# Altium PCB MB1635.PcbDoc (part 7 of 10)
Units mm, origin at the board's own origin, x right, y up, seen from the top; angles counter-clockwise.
Board outline 127 x 97 mm, 6 copper layers (Top Layer, Signal Layer 1, Signal Layer 2, Signal Layer 3, Signal Layer 4, Bottom Layer), stack 1.557 mm thick; 593 components, 478 nets, 2435 pads, 1743 vias.
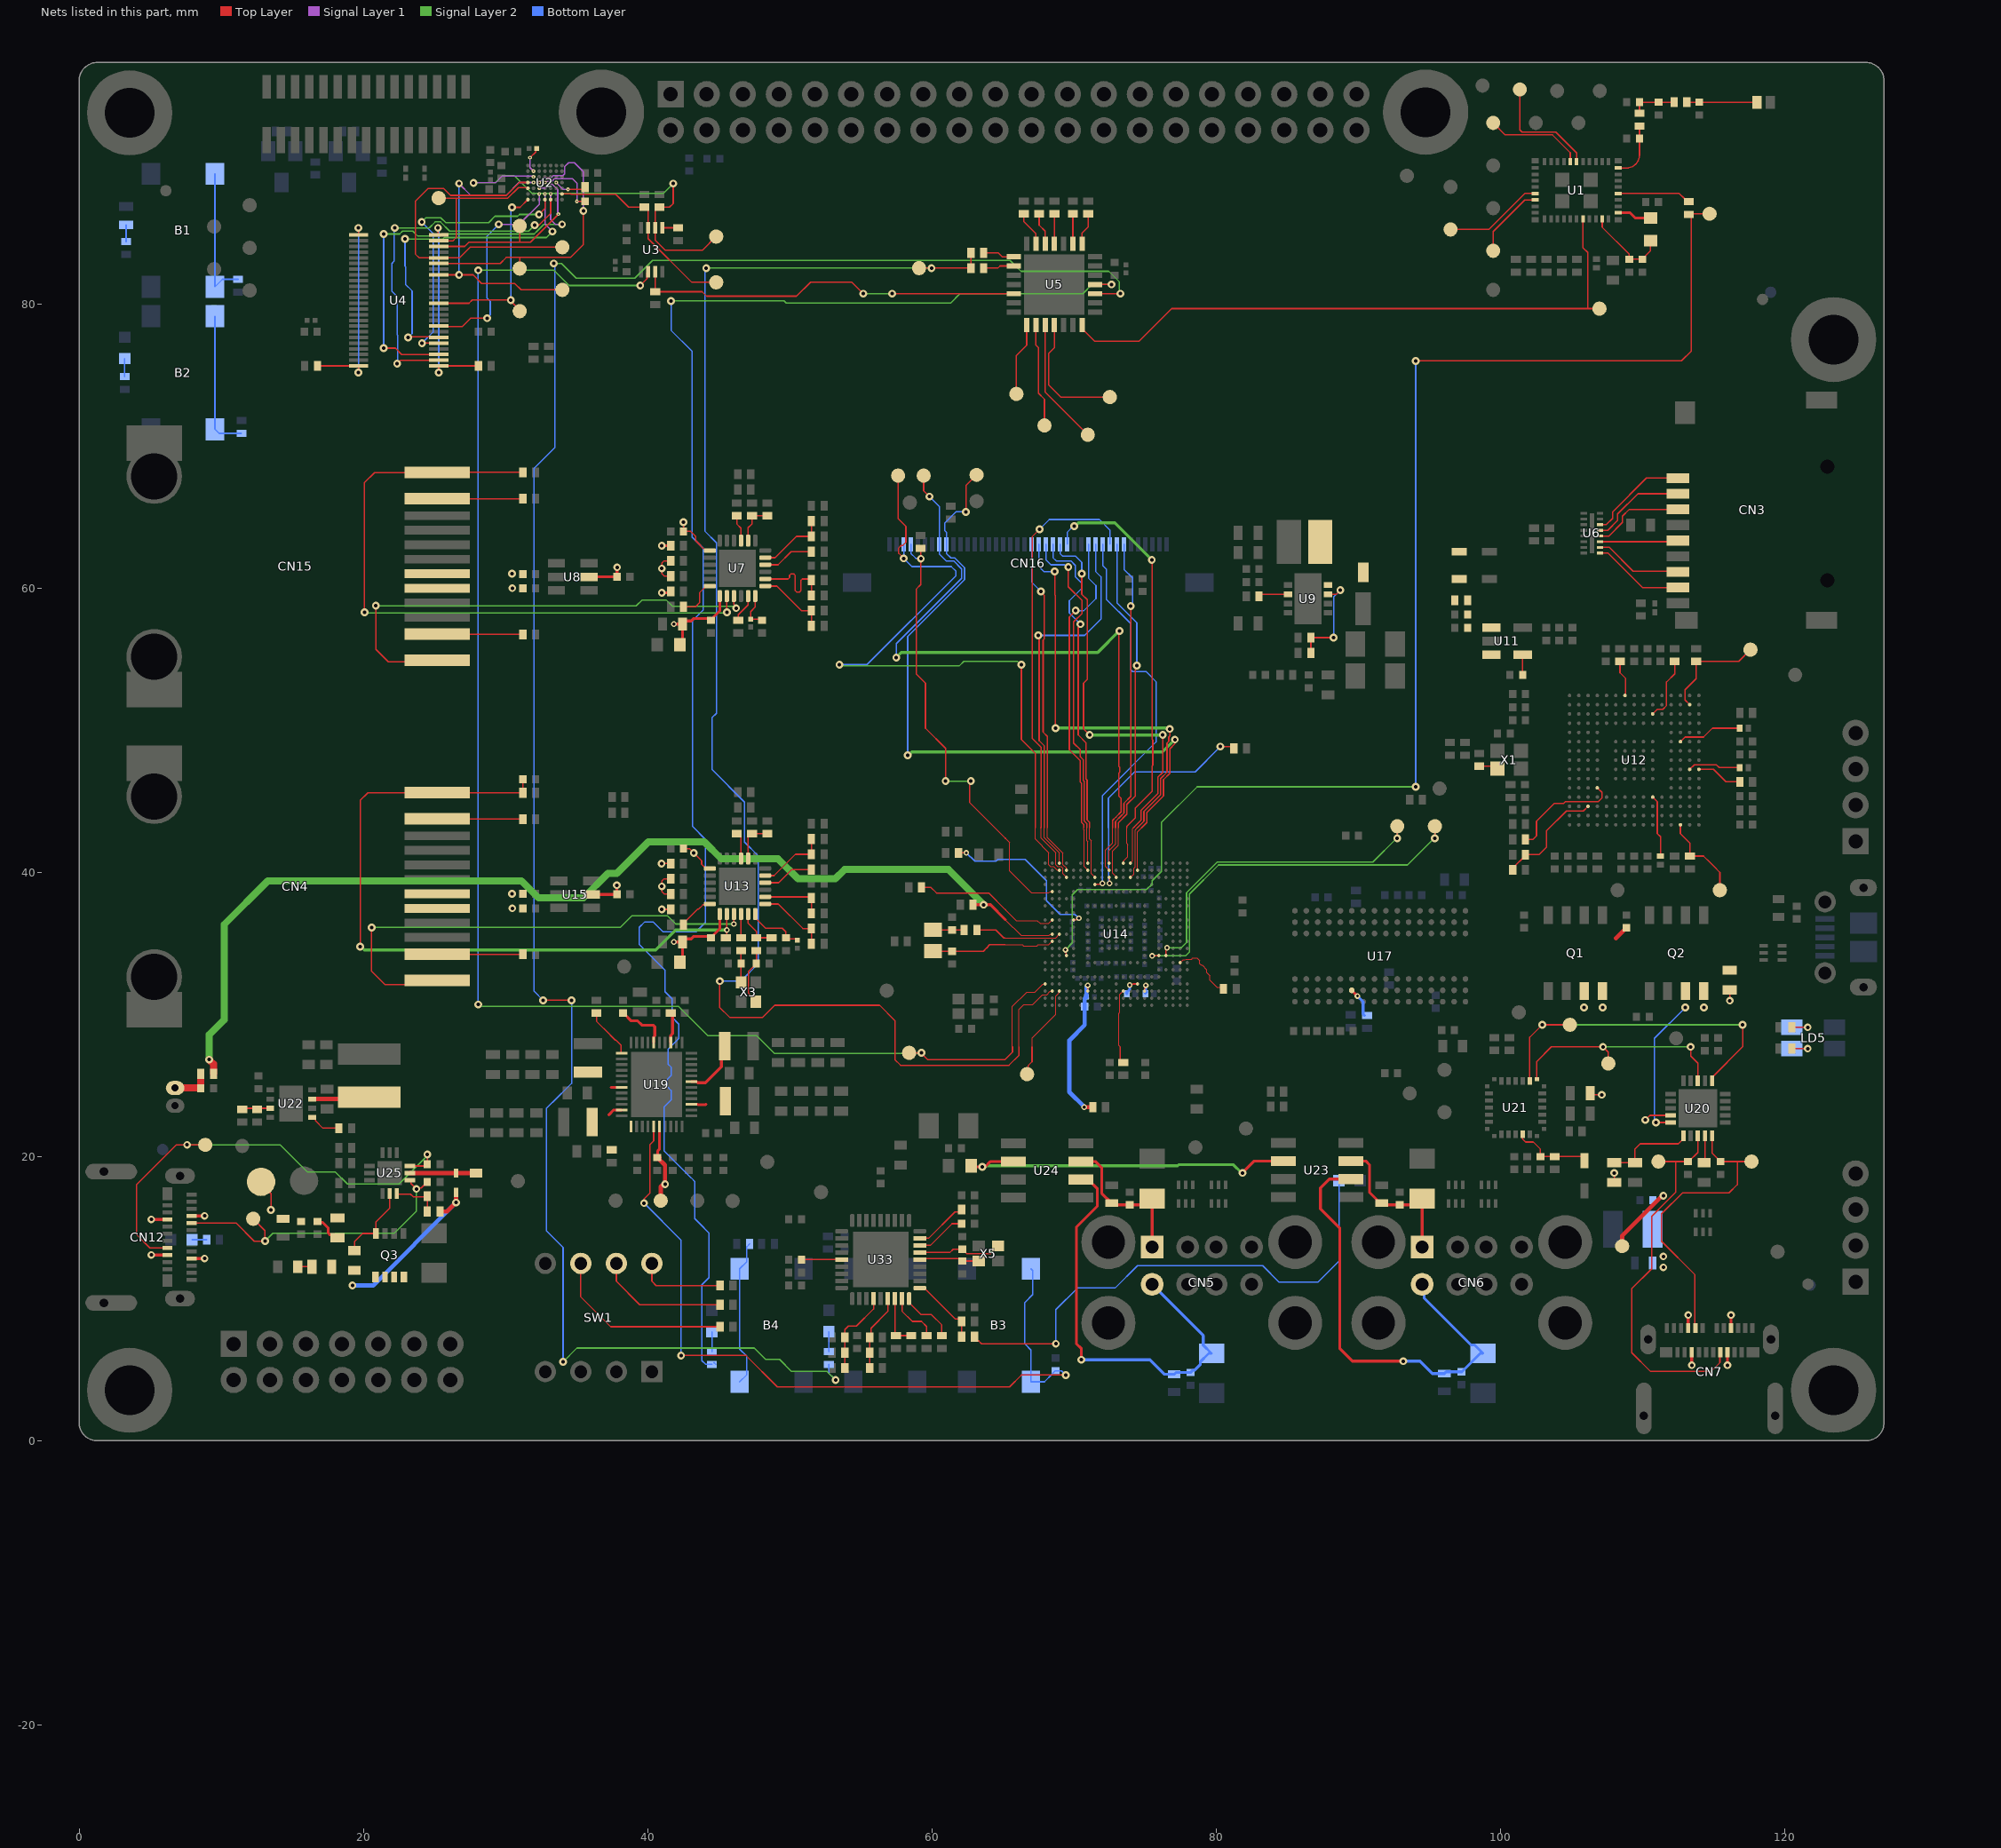
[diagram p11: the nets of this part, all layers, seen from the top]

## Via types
v1: diameter 0.55, hole 0.25, Top Layer to Bottom Layer, 1438 vias
v2: diameter 0.4, hole 0.2, Top Layer to Bottom Layer, 276 vias
v3: diameter 0.26, hole 0.1, Top Layer to Signal Layer 1, tented both sides, 29 vias

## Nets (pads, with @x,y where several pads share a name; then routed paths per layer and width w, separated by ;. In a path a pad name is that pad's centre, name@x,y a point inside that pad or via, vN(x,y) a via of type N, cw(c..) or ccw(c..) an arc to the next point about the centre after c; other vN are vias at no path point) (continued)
LCD_G2: CN16.15 U14.A12 | length 30.4
  Top Layer w0.075: U14.A12@73.475,40.65 73.475,40.775 73.795,41.095 73.795,41.955 73.725,42.025 73.725,43.125
  Top Layer w0.1: 73.725,43.125 73.725,43.249 74.325,43.849 74.325,44.538 75.5,45.713 75.5,47.497 75.55,47.547 75.55,49.33 75.5,49.38 75.5,61.975 v1(75.475,62)
  Signal Layer 2 w0.219: v1(70.025,64.375) 70.094,64.375 70.319,64.6 72.875,64.6 v1(75.475,62)
  Bottom Layer w0.1: CN16.15@69.525,63.1 69.525,63.928 69.972,64.375 v1(70.025,64.375)
LCD_G3: CN16.16 U14.A13 | length 30.2
  Top Layer w0.075: U14.A13@73.975,40.65 74.135,40.81 74.135,43.086 74.174,43.125
  Top Layer w0.1: v1(70.55,61.025) 70.55,59.576 70.937,59.189 70.937,53.587 70.675,53.325 70.675,50.1 v1(71.1,49.675) ; 74.174,43.125 74.25,43.201 74.25,43.208 74.725,43.683 74.725,44.372 75.9,45.547 75.9,46.691 76.25,47.041 v1(76.25,49.675)
  Signal Layer 2 w0.219: v1(71.1,49.675) v1(76.25,49.675)
  Bottom Layer w0.1: CN16.16@69.025,63.1 69.025,62.434 69.2,62.259 70.115,62.259 70.55,61.825 v1(70.55,61.025)
LCD_G4: CN16.17 U14.C8 | length 26.1
  Top Layer w0.075: 71.1,43.125 71.1,42.35 71.221,42.229 71.221,40.752 71.221,40.048 71.221,39.904 U14.C8@71.475,39.65
  Top Layer w0.1: v1(70.45,57.475) 70.45,57.416 70.3,57.266 70.3,49.675 70.853,49.122 70.853,49.06 70.85,49.058 70.85,46.566 70.925,46.491 70.925,43.699 71.1,43.524 71.1,43.125
  Bottom Layer w0.1: CN16.17@68.525,63.1 68.525,62.15 68.75,61.925 69.776,61.925 70.1,61.601 70.1,60.807 70.55,60.357 70.55,59.992 69.675,59.117 69.675,58.25 v1(70.45,57.475)
LCD_G5: CN16.18 U14.A7 | length 24.8
  Top Layer w0.075: 70.9,43.125 70.9,42.225 70.975,42.15 U14.A7@70.975,40.65
  Top Layer w0.1: v1(69.6,61.5) 69.6,60.105 70.575,59.13 70.575,58.225 69.975,57.625 69.975,49.1 70.45,48.625 70.45,48.133 70.65,47.933 70.65,46.483 70.725,46.408 70.725,43.616 70.9,43.441 70.9,43.125
  Bottom Layer w0.1: CN16.18@68.025,63.1 68.025,62 68.375,61.65 69.328,61.65 69.478,61.5 v1(69.6,61.5)
LCD_G6: CN16.19 U14.C13 | length 33.6
  Top Layer w0.075: U14.C13@73.975,39.65 74.221,39.897 74.221,40.296 74.305,40.38 74.305,42.98 74.45,43.125
  Top Layer w0.1: v1(68.65,61.175) 68.65,59.53 68.7,59.48 v1(68.7,50.15) ; 74.45,43.125 74.925,43.6 74.925,44.289 76.1,45.464 76.1,46.608 76.55,47.058 76.55,49.1 76.675,49.225 76.675,49.526 76.744,49.595 v1(76.744,50.1)
  Signal Layer 2 w0.219: v1(68.7,50.15) 68.725,50.175 76.58,50.175 76.655,50.1 v1(76.744,50.1)
  Bottom Layer w0.1: CN16.19@67.525,63.1 67.525,61.53 67.88,61.175 v1(68.65,61.175)
LCD_G7: CN16.20 U14.B4 | length 24.1
  Top Layer w0.075: 68.125,43.125 68.125,42.46 69.225,41.36 69.225,40.55 69.464,40.311 69.464,40.161 U14.B4@69.475,40.15
  Top Layer w0.1: v1@67.655,59.795 67.655,59.74 67.903,59.491 67.903,56.43 67.828,56.355 67.828,49.872 68.125,49.575 68.125,43.125
  Bottom Layer w0.1: CN16.20@67.025,63.1 67.025,60.425 v1(67.675,59.775)
LCD_HSYNC: CN16.32 TP43.1 U14.B14 | length 53
  Top Layer w0.075: U14.B14@74.475,40.15 74.475,42.85 74.75,43.125
  Top Layer w0.1: v1(62.4,65.375) 62.4,67.23 TP43.1@63.145,67.975 ; 74.75,43.125 75.125,43.5 75.125,44.206 76.3,45.381 76.3,46.525 76.75,46.975 76.75,48.7 77.1,49.05 v1(77.1,49.35)
  Signal Layer 2 w0.219: v1(58.3,48.25) 58.369,48.25 58.594,48.475 76.225,48.475 v1(77.1,49.35)
  Bottom Layer w0.1: v1(58.3,48.25) 58.3,56.6 62.3,60.6 62.3,61.441 61.616,62.125 61.34,62.125 61.025,62.44 CN16.32@61.025,63.1 61.025,63.949 60.9,64.074 60.9,64.565 61.71,65.375 v1(62.4,65.375)
LCD_INT: CN16.38 TP42.1 U14.B3 | length 51.5
  Top Layer w0.075: 67.275,43.125 67.275,42.348 68.225,41.398 68.225,40.55 68.35,40.425 68.351,40.425 68.373,40.404 68.571,40.404 68.825,40.15 U14.B3@68.975,40.15
  Top Layer w0.1: TP42.1@57.625,67.925 57.625,64.904 58.175,64.353 58.175,63.225 57.955,63.005 57.855,63.005 57.65,62.8 57.671,62.779 57.671,62.454 v1(58.025,62.1) ; v1(66.3,54.625) 66.3,49.35 67.278,48.372 67.278,43.343 67.275,43.34 67.275,43.125
  Signal Layer 2 w0.1: v1(53.5,54.625) 53.575,54.55 61.95,54.55 62.25,54.85 66.016,54.85 66.241,54.625 v1(66.3,54.625)
  Bottom Layer w0.1: v1(53.5,54.625) 55.442,54.625 61.7,60.883 61.7,61.192 61.367,61.525 58.6,61.525 v1(58.025,62.1) CN16.38@58.025,63.1
LCD_R2: CN16.7 U14.A10 | length 23.4
  Top Layer w0.075: U14.A10@72.475,40.65 72.475,41.55 72.925,42 72.925,43.125
  Top Layer w0.1: 72.925,43.125 72.925,43.58 73.32,43.975 73.32,43.98 73.52,44.18 73.52,44.864 74,45.344 v1(74,58.75)
  Bottom Layer w0.1: CN16.7@73.525,63.1 73.525,61.325 74.125,60.725 74.125,58.997 74,58.872 v1(74,58.75)
LCD_R3: CN16.8 U14.C11 | length 24.8
  Top Layer w0.075: U14.C11@72.975,39.65 72.975,39.681 72.721,39.935 72.721,41.521 73.125,41.925 73.125,43.125
  Top Layer w0.1: 73.125,43.125 73.125,43.497 73.725,44.097 73.725,44.786 74.325,45.386 74.325,54.266 74.339,54.28 74.339,54.464 v1(74.425,54.55)
  Bottom Layer w0.1: CN16.8@73.025,63.1 73.025,58.973 74.425,57.573 v1(74.425,54.55)
LCD_R4: CN16.9 U14.C4 | length 32.4
  Top Layer w0.075: 67.675,43.125 67.675,42.429 68.725,41.379 68.725,40.525 68.85,40.4 69.1,40.4 69.225,40.275 69.225,39.9 U14.C4@69.475,39.65
  Top Layer w0.1: v1(67.579,64.147) 67.053,63.621 67.053,49.447 67.678,48.822 67.678,43.177 67.675,43.174 67.675,43.125
  Bottom Layer w0.1: v1(67.579,64.147) 68.268,64.836 71.794,64.836 72.525,64.105 CN16.9@72.525,63.1
LCD_R5: CN16.10 U14.D8 | length 28
  Top Layer w0.09: U14.D8@71.475,39.15 v2@71.95,39.15
  Bottom Layer w0.09: v2(72,39.225) 72,43.125
  Bottom Layer w0.1: 72,43.125 72,45.4 75.775,49.175 75.775,53.425 75.075,54.125 74.13,54.125 74,54.255 74,57.5 72.275,59.225 72.275,61.355 72.025,61.605 CN16.10@72.025,63.1
LCD_R6: CN16.11 U14.A3 | length 26.9
  Top Layer w0.075: 67.9,43.125 67.9,42.444 68.975,41.369 U14.A3@68.975,40.65
  Top Layer w0.1: v1@67.55,56.6 67.55,49.275 67.9,48.925 67.9,43.125
  Bottom Layer w0.1: v1(67.478,56.678) 70.753,56.678 71.9,57.825 71.9,60.802 71.525,61.177 CN16.11@71.525,63.1
LCD_R7: CN16.12 U14.B7 | length 24.8
  Top Layer w0.075: 70.7,43.125 70.7,43 70.725,42.975 70.725,40.4 U14.B7@70.975,40.15
  Top Layer w0.1: v1(70.125,58.425) 69.675,57.975 69.675,48.625 70.45,47.85 70.45,46.348 70.525,46.273 70.525,43.533 70.7,43.358 70.7,43.125
  Bottom Layer w0.1: v1(70.125,58.425) 70.7,58.425 71.55,59.275 71.55,60.18 71.025,60.705 CN16.12@71.025,63.1
LCD_RST: CN16.37 R58.1 U14.E2 | length 31.9
  Top Layer w0.075: 65.175,42.4 65.46,42.115 65.46,40.115 67.009,38.566 68.222,38.566 68.305,38.649 68.474,38.649 U14.E2@68.475,38.65
  Top Layer w0.1: R58.1@59.2,62.8 59.225,62.775 v1(59.225,62.075) 59.225,60.25 58.9,59.925 58.9,53.975 59.55,53.325 59.55,50.15 60.971,48.729 v1(60.971,46.425) ; v1(62.75,46.425) 62.664,46.339 62.664,46.155 62.65,46.141 62.65,44.925 65.175,42.4
  Signal Layer 2 w0.1: v1(60.971,46.425) v1(62.75,46.425)
  Bottom Layer w0.1: CN16.37@58.525,63.1 58.525,62.451 58.862,62.114 59.186,62.114 v1(59.225,62.075)
LCD_VSYNC: CN16.33 TP37.1 U14.B10 | length 50.2
  Top Layer w0.075: U14.B10@72.475,40.15 72.225,40.4 72.225,41.575 72.725,42.075 72.725,43.125
  Top Layer w0.1: TP37.1@59.425,67.925 59.425,66.85 v1(59.825,66.45) ; 72.725,43.125 72.725,43.663 72.963,43.9 72.963,43.905 73.32,44.262 73.32,45.205 73.15,45.375 73.15,46.974 73.225,47.049 73.225,47.401 73.15,47.476 73.15,56.95 v1(73.2,57)
  Signal Layer 2 w0.219: v1(57.5,55.125) 57.846,55.471 71.671,55.471 v1(73.2,57)
  Bottom Layer w0.1: v1(57.5,55.125) 57.5,56.1 62.1,60.7 62.1,61.358 61.533,61.925 61.009,61.925 60.525,62.409 CN16.33@60.525,63.1 60.525,65.75 v1(59.825,66.45)
LED_G: R183.1 U5.3 | length 147.3
  Top Layer w0.1: v1(32.65,31) v1(34.65,31) ; U5.3@71.475,80.725 v1(73.275,80.725)
  Signal Layer 2 w0.1: v1(33.4,82.85) 33.95,82.85 34.975,81.825 39.105,81.825 40.355,83.075 65.5,83.075 66.275,82.3 72.45,82.3 73.2,81.55 73.2,80.8 v1(73.275,80.725) ; v1(34.05,5.55) 35.025,6.525 47.5,6.525 48.3,5.725 49.283,5.725 50.133,4.875 52.634,4.875 53.225,4.284 v1(53.225,4.275)
  Bottom Layer w0.1: v1(32.65,31) 32,31.65 32,68.425 33.475,69.9 33.475,82.775 v1(33.4,82.85) ; v1(34.05,5.55) 34.05,13.6 32.875,14.775 32.875,23.4 33.3,23.825 33.326,23.825 34.65,25.149 v1(34.65,31) ; R183.1@52.75,5.375 52.75,4.75 v1(53.225,4.275)
LED_Y: R184.1 U5.4 | length 118.5
  Top Layer w0.1: U5.4@71.475,81.375 v1(72.65,81.375)
  Signal Layer 2 w0.1: v1(41.65,80.2) 41.675,80.225 49.6,80.225 49.75,80.075 61.325,80.075 61.975,80.725 70.625,80.725 71.275,81.375 v1(72.65,81.375)
  Bottom Layer w0.1: v1(41.65,80.2) 41.65,78.15 43.125,76.675 43.125,63.6 43.905,62.82 43.905,58.455 43.15,57.7 43.15,43.25 44.075,42.325 44.075,36.476 43.419,35.82 41.08,35.82 40.38,36.52 39.8,36.52 39.41,36.13 39.41,35.914 39.4,35.904 39.4,34.949 41.227,33.122 41.227,31.601 41.725,31.103 41.725,29.8 42.2,29.325 42.2,28.3 41.45,27.55 41.45,26.5 41.65,26.3 41.65,25.7 41.375,25.425 41.375,24.925 41.65,24.65 41.65,23.975 41.15,23.475 41.15,20.425 43.075,18.5 ; 43.076,18.5 43.325,18.251 43.325,15.627 43.625,15.327 43.625,15.325 44.325,14.625 44.325,11.475 43.825,10.975 43.825,5.642 44.084,5.383 44.517,5.383 R184.1@44.525,5.375 ; R184.1@44.662,5.513 R184.1@44.8,5.375
LPO_32: R190.1 TP15.1 U14.P4 | length 94.6
  Top Layer w0.09: v2@69.45,34.55 69.45,34.175 U14.P4@69.475,34.15
  Top Layer w0.1: v1(94.05,76) 112.75,76 113.45,76.7 113.45,86.125 113.363,86.212 113.5,86.35 TP15.1@114.725,86.35
  Signal Layer 2 w0.09: v2(69.4,34.55) 69.875,35.025 69.875,38.4 70.25,38.775 75.1,38.775 75.5,39.175 75.5,39.425 76.15,40.075 76.15,43.125
  Signal Layer 2 w0.1: 76.15,43.125 76.15,43.5 78.675,46.025 v1(94.05,46.025)
  Bottom Layer w0.1: v1(94.05,46.025) v1(94.05,76)
MCO1: TP54.1 U3.2 U14.V1 | length 111.2
  Top Layer w0.075: 65.675,27.725 65.675,30.575 66.675,31.575 67.261,31.575 67.813,32.127 67.952,32.127 U14.V1@67.975,32.15
  Top Layer w0.1: v1(39.475,81.3) 39.959,81.784 39.959,82.184 U3.2@40.04,82.265 ; TP54.1@58.4,27.3 v1(59.275,27.3) ; v1@59.225,27.3 59.7,26.825 65.15,26.825 65.675,27.35 65.675,27.725
  Signal Layer 2 w0.1: v1(28.076,30.701) 28.076,30.699 28.2,30.575 42.175,30.575 44.25,28.5 47.7,28.5 48.95,27.25 59.175,27.25 v1@59.225,27.3 ; v1(28.076,82.379) 33.396,82.379 34.475,81.3 v1(39.475,81.3)
  Bottom Layer w0.1: v1(28.076,30.701) 28.076,82.301 v1(28.076,82.379)
MCP_INT: R12.1 R19.1 TP23.1 U14.W2 | length 107.9
  Top Layer w0.075: 66.125,27.725 66.125,30.35 66.475,30.7 67.103,30.7 67.8,31.397 68.097,31.397 68.327,31.627 68.452,31.627 U14.W2@68.475,31.65
  Top Layer w0.1: v1(45.075,32.35) 45.075,30.5 45.775,29.8 48.1,29.8 48.95,30.65 56.325,30.65 57.4,29.575 57.4,26.825 57.8,26.425 65.425,26.425 66.125,27.125 66.125,27.725 ; TP23.1@59.1,82.525 v1(59.975,82.525) R19.1@62.75,82.525 R12.1@62.75,83.6
  Signal Layer 2 w0.1: v1(44.125,82.525) v1(59.975,82.525)
  Bottom Layer w0.1: v1(44.125,82.525) 44.039,82.439 44.039,82.255 44.025,82.241 44.025,64.025 44.85,63.2 44.85,51.2 44.525,50.875 44.525,47.25 46.825,44.95 46.825,42.125 47.775,41.175 47.775,33.55 46.575,32.35 v1(45.075,32.35)
MCP_IO2: R13.2 U3.3 U5.19 | length 27.5
  Top Layer w0.1: U3.3@40.54,82.265 R13.2@40.54,80.865 43.835,80.865 44.15,80.55 50.475,80.55 51.467,81.542 54.358,81.542 v1(55.175,80.725) ; v1(57.2,80.725) U5.19@65.775,80.725
  Signal Layer 2 w0.1: v1(55.175,80.725) v1(57.2,80.725)
MCP_IO11: TP30.1 U1.28 U5.28 | length 44.4
  Top Layer w0.1: U5.28@70.575,78.525 70.575,78.25 71.45,77.375 74.575,77.375 76.875,79.675 106.15,79.675 ; U1.28@105.825,85.975 105.825,83.95 106.15,83.625 106.15,79.675 ; TP30.1@106.975,79.675 106.15,79.675
NetB1_3: B1.3 B1.4 R173.1 | length 9.8
  Bottom Layer w0.1: B1.3@9.555,89.163 B1.4@9.555,81.213 10.08,81.738 R173.1@11.18,81.738
NetB2_3: B2.3 B2.4 R175.1 | length 9.9
  Bottom Layer w0.1: B2.3@9.555,79.138 B2.4@9.555,71.188 9.843,70.9 R175.1@11.425,70.9
NetB3_3: B3.3 B3.4 C228.2 U19.17 | length 57.1
  Top Layer w0.1: v1(39.75,16.725) 39.75,17.025 40.15,17.425 40.15,20.825 40.425,21.1 U19.17@40.425,22.125 ; v1(42.35,6) 46.925,6 49.125,3.8 65.475,3.8 66.3,4.625 v1(69.425,4.625)
  Bottom Layer w0.1: v1(39.75,16.725) 42.35,14.125 v1(42.35,6) ; B3.3@66.975,12.1 67.1,11.975 67.1,10.284 66.543,9.728 66.543,6.825 66.975,6.393 B3.4@66.975,4.15 67.925,4.15 68.47,4.695 68.47,4.72 68.675,4.925 C228.2@68.7,4.925 69.125,4.925 v1(69.425,4.625)
NetB4_3: B4.3 B4.4 R182.1 | length 10.4
  Bottom Layer w0.1: B4.3@46.475,4.15 46.983,4.658 46.983,5.942 46.475,6.45 B4.4@46.475,12.1 46.982,12.607 46.982,13.657 R182.1@47.175,13.85
NetC1_2: C1.2 C2.2 R1.2 R2.1 | length 3.2
  Top Layer w0.1: R2.1@109.8,93.425 C1.2@109.8,94.2 R1.2@112.225,94.2
NetC3_2: C3.2 L1.1 R1.1 | length 4.9
  Top Layer w0.1: R1.1@113.125,94.2 C3.2@114,94.2 L1.1@118.05,94.2
NetC4_2: C4.2 R2.2 U1.41 | length 4.1
  Top Layer w0.1: U1.41@108.3,89.575 108.888,89.575 ccw(c108.888,90.487) 109.8,90.487 C4.2@109.8,91.65 R2.2@109.8,92.525
NetC5_2: C5.2 U2.F2 | length 1.9
  Top Layer w0.1: v3(31.725,90.3) 32.125,90.7 32.125,90.875 C5.2@32.2,90.95
  Signal Layer 1 w0.1: v3(31.725,90.3) 31.725,89.6 v3(31.975,89.35)
NetC14_2: C14.2 U2.D4 | length 4.4
  Top Layer w0.1: v3(35.025,87.225) C14.2@35.6,87.225
  Signal Layer 1 w0.1: v3(32.775,88.55) 32.818,88.55 32.898,88.63 33.25,88.63 33.45,88.83 34.7,88.83 35.025,88.505 v3(35.025,87.225)
NetC20_2: C20.2 C21.2 L2.2 U1.31 | length 6.1
  Top Layer w0.1: U1.31@107.175,85.975 107.175,85.4 109.075,83.5 C20.2@109.075,83.15 C21.2@110,83.15 110,83.175 110.575,83.75 L2.2@110.575,84.45
NetC28_2: C28.2 C32.2 C33.1 C35.2 C37.2 C39.1 CN15.5 CN15.6 L4.1 R37.2 R39.2 R40.2 R42.2 U7.1 U7.19 U8.5 | length 15.5
  Top Layer w0.1: R40.2@41.625,60.85 41.175,60.85 41,61.025 v1(41,61.388) 41,61.775 41.15,61.925 R39.2@41.625,61.925 ; v1(42.525,64.65) C28.2@42.525,64 43.025,64 43.375,63.65 43.375,63.35 44.075,62.65 U7.19@44.375,62.65
  Top Layer w0.2: U8.5@35.875,60.8 C33.1@37.85,60.8 v1(37.85,61.475) ; v1(41,59.675) 41.525,59.675 R42.2@41.625,59.775 ; v1(41,63) R37.2@41.625,63 ; v2(41.85,57.475) C39.1@42.45,57.475 ; L4.1@42.275,56.05 42.45,56.225 C39.1@42.45,57.475 ; U7.1@45.075,59.45 45.075,58.4 44.45,57.775 44.35,57.875 43.25,57.875 43.075,57.7 42.675,57.7 C39.1@42.45,57.475
  other v1: 30.475,60.005 30.45,61.03
NetC36_1: C36.1 C41.2 R45.2 U11.1 U11.3
NetC38_2: C38.2 C40.2 U7.6 | length 2.6
  Top Layer w0.1: U7.6@47.575,59.45 47.575,58.675 47.25,58.35 C40.2@47.25,57.825 47.975,57.825 C38.2@48.05,57.75
NetC55_2: C55.2 U11.4 | length 1.4
  Top Layer w0.1: C55.2@101.575,53.9 U11.4@101.575,55.325
NetC60_2: C60.2 U12.F13 | length 4.6
  Top Layer w0.1: U12.F13@112.675,49.2 113,49.525 114.3,49.525 114.925,50.15 C60.2@116.85,50.15
NetC64_2: C64.2 U12.J14 | length 3.7
  Top Layer w0.1: U12.J14@113.325,47.25 113.65,47.575 115.2,47.575 115.4,47.375 C64.2@116.85,47.375
NetC71_2: C71.2 C80.2 C81.1 C85.2 C89.2 C91.1 CN4.5 CN4.6 L5.1 R92.2 R95.2 R97.2 R99.2 U13.1 U13.19 U15.5 | length 14.7
  Top Layer w0.1: v1(40.975,40.625) R92.2@41.625,40.625 ; v1(41,37.4) R99.2@41.625,37.4 ; R97.2@41.625,38.475 41.175,38.475 41,38.65 v1(41,39.013) 41,39.4 41.15,39.55 R95.2@41.625,39.55 ; C71.2@42.525,41.675 42.95,41.675 v1(43.25,41.375) 43.8,40.825 43.8,40.575 44.1,40.275 U13.19@44.375,40.275
  Top Layer w0.2: U15.5@36.05,38.45 C81.1@37.85,38.45 37.825,38.475 v1(37.825,39.1) ; v2(41.85,35.1) C91.1@42.45,35.1 ; L5.1@42.275,33.675 42.45,33.85 C91.1@42.45,35.1 ; U13.1@45.075,37.075 45.075,36.025 C89.2@44.45,35.4 44.35,35.5 43.25,35.5 43.075,35.325 42.675,35.325 C91.1@42.45,35.1
  other v1: 30.475,37.475 30.45,38.5
NetC73_2: C73.2 U12.M10 | length 4.4
  Top Layer w0.1: U12.M10@110.725,45.3 111.05,44.975 111.05,42.725 111.275,42.5 C73.2@111.275,41.15
NetC83_2: C83.2 CN11.1 R191.2 | length 2.8
  Top Layer w0.5: CN11.1@6.75,24.825 8.545,24.825 C83.2@8.55,24.82 ; C83.2@8.55,24.8 C83.2@8.55,24.82 ; R191.2@8.55,25.825 C83.2@8.55,24.82
NetC87_2: C87.2 Q1.7 Q1.8 Q2.7 Q2.8 R111.2 U20.10 | length 11.1
  Top Layer w0.1: v1(110.95,22.4) U20.10@111.975,22.4
  Top Layer w0.3: 108.15,35.375 C87.2@108.875,36.1
  Bottom Layer w0.1: v1(110.95,22.4) 110.864,22.486 110.864,22.67 110.85,22.684 110.85,28.325 v1(113.025,30.5)
  other v1: 105.9,30.5 107.2,30.5 114.325,30.5
NetC88_1: C88.1 R103.2 X2.1 | length 2.2
  Top Layer w0.1: X2.1@60.075,35.95 C88.1@61.425,35.95 R103.2@62.275,35.95
NetC90_2: C90.2 C92.2 U13.6 | length 4.1
  Top Layer w0.1: U13.6@47.575,37.075 47.575,36.8 48.3,36.075 49.475,36.075 49.725,35.825 C90.2@49.725,35.4 49.8,35.325 50.425,35.325 C92.2@50.525,35.225
NetC93_1: C93.1 U14.M2 X2.2 | length 8.8
  Top Layer w0.075: 65.175,34.9 66.369,34.9 66.45,34.819 67.394,34.819 67.475,34.9 68.225,34.9 U14.M2@68.475,35.15
  Top Layer w0.09: 63.85,34.675 64.075,34.9 65.175,34.9
  Top Layer w0.1: X2.2@60.075,34.45 C93.1@61.425,34.45 63.625,34.45 63.85,34.675
NetC95_2: C95.2 R105.1 X3.3 | length 2.3
  Top Layer w0.1: X3.3@46.575,32.25 C95.2@46.575,33.6 R105.1@46.575,34.5
NetC96_2: C96.2 R106.1 X3.1 | length 4.1
  Top Layer w0.1: X3.1@47.625,30.975 X3.1@47.625,30.9 47.3,31.225 47.3,31.3 47.1,31.5 47.1,33.025 47.65,33.575 C96.2@47.65,33.6 R106.1@47.65,34.5
NetC99_1: C99.1 U19.40 | length 3.8
  Top Layer w0.2: C99.1@38.275,30.1 38.3,30.1 38.85,29.55 39.3,29.55 39.599,29.251 40.383,29.251 40.5,29.134 40.5,28.498 40.425,28.423 U19.40@40.425,28.025
NetC136_2: C136.2 C152.2 CN5.T1 U24.7 U30.1 | length 11
  Top Layer w0.2: U24.7@70.475,19.66 71.515,19.66 71.95,19.225 71.95,17.425 U30.1@72.65,16.725 72.775,16.6 C152.2@73.925,16.6 75.05,16.6 C136.2@75.5,17.05 CN5.T1@75.5,13.63
NetC137_2: C137.2 C153.2 CN6.T1 U23.7 U31.1 | length 11.1
  Top Layer w0.2: U23.7@89.475,19.685 90.54,19.685 90.8,19.425 90.8,17.475 91.55,16.725 U31.1@91.65,16.725 91.775,16.6 C153.2@92.925,16.6 94.05,16.6 C137.2@94.5,17.05 CN6.T1@94.5,13.63
NetC140_2: C140.2 D4.1 R141.1 U21.5 | length 5.8
  Top Layer w0.1: U21.5@101.575,21.575 101.575,21.225 101.775,21.025 102.325,21.025 102.825,20.525 C140.2@102.825,20 R141.1@103.825,20 105.925,20 D4.1@105.925,19.72
NetC142_2: C142.2 TP70.1 U19.18 | length 5.8
  Top Layer w0.2: C142.2@40.7,19.925 40.7,20.375 40.825,20.5 U19.18@40.825,22.125
  Top Layer w0.3: C142.2@40.825,19.925 40.7,19.925 41.225,19.4 41.225,18.235 41.252,18.208 41.225,18.182 v1(41.225,18.052) 41.102,18.052 40.925,17.875 TP70.1@40.925,16.9
NetC147_2: C147.2 CN7.B5 TP64.1 U20.13 | length 26.7
  Top Layer w0.1: TP64.1@111.125,19.65 112.35,19.65 ; 111.625,16.775 110.65,15.8 110.65,12.109 109.25,10.709 109.25,6.2 110.575,4.875 114.825,4.875 115.45,5.5 115.45,6.21 CN7.B5@115.475,6.235 ; 111.626,16.775 112.35,17.499 112.35,19.65 ; U20.13@113.9,21.475 113.9,20.3 113.25,19.65 C147.2@113.2,19.65 112.35,19.65
NetC148_2: C148.2 CN7.A5 TP65.1 U20.15 | length 21.1
  Top Layer w0.1: CN7.A5@113.725,7.935 113.7,7.96 113.7,11.688 111.35,14.038 111.35,15.975 112.825,17.45 116.1,17.45 116.675,18.025 116.675,19.65 ; U20.15@114.9,21.475 114.9,20.25 C148.2@115.5,19.65 116.675,19.65 ; TP65.1@117.675,19.65 116.675,19.65
NetC149_2: C149.2 U20.14 | length 1.9
  Top Layer w0.1: C149.2@114.35,19.575 114.4,19.625 U20.14@114.4,21.475
NetC151_2: C151.2 CN12.B5 TP73.1 U25.9 | length 32.6
  Top Layer w0.1: CN12.B5@6.21,13.575 4.975,13.575 4.05,14.5 4.05,18.04 6.838,20.828 v1(7.597,20.828) TP73.1@8.456,20.828 ; U25.9@23.27,19.339 24.37,19.339 C151.2@24.495,19.464 24.5,19.47 v1(24.5,20.15)
  Signal Layer 2 w0.1: v1(7.597,20.828) 14.147,20.828 16.05,18.925 18.025,18.925 18.875,18.075 22.505,18.075 24.5,20.07 v1(24.5,20.15)
NetC155_1: C155.1 D5.2 U25.8 | length 4.6
  Top Layer w0.3: U25.8@23.27,18.839 D5.2@26.52,18.839 C155.1@27.92,18.839
NetC156_2: C156.2 CN12.A5 TP77.1 U25.7 | length 22.6
  Top Layer w0.1: CN12.A5@7.91,15.325 11.05,15.325 12.325,14.05 v1(13.076,14.05) 13.076,14.799 TP77.1@12.25,15.625 ; U25.7@23.27,18.339 U25.7@23.352,18.257 ; U25.7@23.359,18.25 U25.7@23.352,18.257 ; C156.2@24.459,18.25 C156.2@24.495,18.214 ; C156.2@24.5,18.225 24.5,18.195 24.29,17.984 24.259,17.984 24.063,17.788 23.788,17.788 v1(23.725,17.725) 23.352,18.098 U25.7@23.352,18.257
  Signal Layer 2 w0.1: v1(13.076,14.05) 13.626,14.6 22.175,14.6 23.725,16.15 23.725,16.6 v1(23.725,17.725)
NetC158_2: C158.2 U33.34 | length 3.6
  Top Layer w0.1: U33.34@59.15,13.75 59.9,13.75 61.425,15.275 C158.2@62.1,15.275
NetC159_2: C159.2 U33.33 X5.1 | length 5.9
  Top Layer w0.1: U33.33@59.15,13.25 61.275,13.25 61.5,13.475 C159.2@62.15,13.475 62.45,13.175 64.125,13.175 X5.1@64.65,13.7
NetC160_1: C160.1 C167.2 D5.1 Q3.5 Q3.6 Q3.7 Q3.8 R150.2 R151.2 R185.2 | length 13.9
  Top Layer w0.2: C160.1@16.77,15.439 16.841,15.368 17.141,15.368 17.52,14.989 17.52,14.623 17.628,14.514 17.652,14.514 17.657,14.509 17.95,14.509 R151.2@18.17,14.289
  Top Layer w0.3: R150.2@25.395,16.139 25.895,16.139 v1(26.52,16.764) D5.1@26.52,17.489
  Bottom Layer w0.3: v1(19.225,10.929) 20.684,10.929 v1(26.52,16.764)
NetC161_2: C161.2 CN12.A4 CN12.A9 CN12.B4 CN12.B9 R151.1 TP68.1 U34.1 | length 6.4
  Top Layer w0.1: TP68.1@12.8,18.225 12.8,18.081 13.5,17.381 v1(13.5,16.25)
  Top Layer w0.2: v1(5.075,13.075) CN12.B4@6.21,13.075 ; v1(5.075,15.575) CN12.B9@6.21,15.575 ; CN12.A9@7.91,12.825 v1(8.825,12.825) ; CN12.A4@7.91,15.825 v1(8.825,15.825)
NetC163_2: C163.2 U33.14 | length 2.8
  Top Layer w0.1: C163.2@50.825,12.75 U33.14@53.65,12.75
NetC164_2: C164.2 U33.32 X5.3 | length 4.3
  Top Layer w0.1: U33.32@59.15,12.75 59.225,12.825 61.975,12.825 C164.2@62.15,12.65 X5.3@63.3,12.65
NetC166_2: C166.2 R185.1 | length 1
  Top Layer w0.1: C166.2@15.375,12.25 R185.1@16.375,12.25
NetC167_1: C167.1 Q3.4 U25.5 | length 5.8
  Top Layer w0.1: C167.1@19.37,13.139 19.37,14.014 19.945,14.589 Q3.4@20.87,14.589 20.87,15.389 21.845,16.364 U25.5@21.845,17.414
NetC216_1: C216.1 U14.W15 | length 1
  Top Layer w0.1: U14.W15@74.974,31.65 74.975,31.919 75.054,31.997 v2(75.054,32.051)
  Bottom Layer w0.2: C216.1@75.025,31.5 75.1,31.575 75.054,31.621 v2(75.054,32.051)
NetC217_1: C217.1 U14.V14 | length 1.3
  Top Layer w0.1: v2(73.925,32.075) 74.081,32.075 74.156,32.15 U14.V14@74.474,32.15
  Bottom Layer w0.2: C217.1@73.725,31.475 73.725,31.575 73.925,31.775 v2(73.925,32.075)
NetC219_1: C219.1 C220.2 R133.1 U14.W7 | length 10.5
  Top Layer w0.09: U14.W7@70.975,31.65 v2(70.975,32.05)
  Top Layer w0.3: v2@70.75,23.475 R133.1@71.325,23.475
  Bottom Layer w0.3: v2@70.725,23.5 69.675,24.55 69.675,28.175 70.755,29.255 C220.2@70.755,30.545 70.755,31.12 C219.1@70.88,31.245 70.88,31.955 v2(70.975,32.05)
  other v2: 70.725,23.475
NetC221_2: C221.2 C222.2 CN7.A4 CN7.A9 CN7.B4 CN7.B9 R111.1 R129.2 R142.2 TP74.1 U20.9 U36.1 | length 12.7
  Top Layer w0.1: R129.2@106.325,24.45 106.425,24.35 v1(107.15,24.35) ; v1(108.025,18.85) R142.2@108.025,18.175 108.025,18.125 R142.2@108.05,18.1 ; v1(110.2,22.575) 110.525,22.9 U20.9@111.975,22.9 ; v1(116.15,30.975) R111.1@116.15,31.725
  Top Layer w0.2: CN7.A4@113.225,7.935 v1(113.225,8.85) ; v1(113.475,5.32) CN7.B9@113.475,6.235 ; v1(115.975,5.32) CN7.B4@115.975,6.235 ; CN7.A9@116.225,7.935 v1(116.225,8.85)
  Top Layer w0.3: TP74.1@108.575,13.7 108.584,13.709 108.584,14.434 111.381,17.231 111.456,17.231 v1(111.475,17.25)
  other v1: 111.475,12.2 111.475,12.975
NetC224_2: C224.2 C226.2 CN6.B1 U23.6 U38.1 | length 32.4
  Top Layer w0.2: U23.6@89.475,18.415 87.965,18.415 87.35,17.8 87.35,16.325 88.7,14.975 88.7,6.5 89.6,5.6 v1(93.175,5.6)
  Bottom Layer w0.2: v1(93.175,5.6) 94.35,5.6 95.225,4.725 U38.1@96.075,4.725 96.2,4.85 C226.2@97.275,4.85 97.3,4.85 97.455,5.005 97.985,5.535 97.985,5.55 98.585,6.15 C224.2@98.775,6.15 98.175,6.75 97.925,6.75 94.648,10.027 94.648,10.862 CN6.B1@94.5,11.01
NetC225_2: C225.2 C227.2 CN5.B1 U24.6 U39.1 | length 31.1
  Top Layer w0.2: U24.6@70.475,18.39 70.985,18.39 71.65,17.725 71.65,16.525 70.175,15.05 70.175,6.825 70.525,6.475 v1(70.525,5.7)
  Bottom Layer w0.2: v1(70.525,5.7) 75.35,5.7 76.375,4.675 U39.1@77.05,4.675 77.175,4.8 C227.2@78.2,4.8 78.355,4.955 78.48,4.955 78.885,5.36 78.885,5.55 79.485,6.15 C225.2@79.675,6.15 79.1,6.725 79.1,7.41 CN5.B1@75.5,11.01
NetC229_2: C229.2 CN4.12 R70.2 R104.2 U13.2 | length 51.1
  Top Layer w0.1: v1(19.775,34.775) 19.775,45.075 20.31,45.61 CN4.12@25.2,45.61 31.215,45.61 R70.2@31.225,45.6 C229.2@31.225,46.55 ; R104.2@45.5,35.4 45.575,35.475 v2(45.575,35.95) U13.2@45.575,37.075
  Signal Layer 2 w0.219: v1(19.775,34.775) 19.844,34.775 20.069,34.55 23.717,34.55 40.575,34.55 41.975,35.95 v2(45.575,35.95)
NetCN3_1: CN3.1 U6.14 | length 7.1
  Top Layer w0.1: U6.14@107.025,64.475 107.46,64.475 107.9,64.915 107.9,65.365 110.285,67.75 CN3.1@112.5,67.75
NetCN3_2: CN3.2 U6.13 | length 6.8
  Top Layer w0.1: U6.13@107.025,64.075 107.555,64.075 108.25,64.77 108.25,65.22 109.68,66.65 CN3.2@112.5,66.65
NetCN3_3: CN3.3 U6.12 | length 6.5
  Top Layer w0.1: U6.12@107.025,63.675 107.65,63.675 108.6,64.625 108.6,65.075 109.075,65.55 CN3.3@112.5,65.55
NetCN3_5: CN3.5 U6.11 | length 5.5
  Top Layer w0.1: U6.11@107.025,63.275 112.425,63.275 CN3.5@112.5,63.35
NetCN3_7: CN3.7 U6.10 | length 6.2
  Top Layer w0.1: U6.10@107.025,62.875 107.675,62.875 109.35,61.2 112.45,61.2 CN3.7@112.5,61.15
NetCN3_8: CN3.8 U6.9 | length 6.5
  Top Layer w0.1: U6.9@107.025,62.475 107.575,62.475 110,60.05 CN3.8@112.5,60.05
NetCN4_1: CN4.1 U13.3 | length 35
  Top Layer w0.1: v1(20.575,36.125) 20.575,33.05 21.525,32.1 24.91,32.1 CN4.1@25.2,32.39 ; v2(46.072,36.371) 46.072,37.072 U13.3@46.075,37.075
  Signal Layer 2 w0.1: v1(20.575,36.125) 38.075,36.125 38.9,36.95 41.4,36.95 41.979,36.371 v2(46.072,36.371)
NetCN4_2: CN4.2 R110.2 | length 4
  Top Layer w0.1: CN4.2@27.2,34.23 31.205,34.23 R110.2@31.225,34.25
NetCN4_11: CN4.11 R76.2 | length 6
  Top Layer w0.1: CN4.11@25.2,43.77 31.205,43.77 R76.2@31.225,43.75
NetCN15_1: CN15.1 U7.3 | length 34.5
  Top Layer w0.1: v1(20.875,58.775) 20.875,55.7 21.75,54.825 25.105,54.825 CN15.1@25.2,54.92 ; U7.3@46.075,59.45 46.075,58.872 46.225,58.722 v1(46.225,58.6)
  Signal Layer 2 w0.1: v1@20.875,58.75 39.197,58.75 39.622,59.175 41.3,59.175 41.75,58.725 46.1,58.725 v1(46.225,58.6)
NetCN15_2: CN15.2 R52.2 | length 6
  Top Layer w0.1: CN15.2@25.2,56.76 31.215,56.76 R52.2@31.225,56.75
NetCN15_11: CN15.11 R27.2 | length 6
  Top Layer w0.1: CN15.11@25.2,66.3 R27.2@31.225,66.3
NetCN15_12: CN15.12 R24.2 U7.2 | length 47.3
  Top Layer w0.1: v1(20.075,58.3) 20.075,67.429 20.786,68.14 CN15.12@25.2,68.14 25.222,68.162 31.213,68.162 R24.2@31.225,68.15 ; v1(45.575,58.3) U7.2@45.575,59.45
  Signal Layer 2 w0.1: v1(20.075,58.3) 20.125,58.25 45.525,58.25 v1(45.575,58.3)
NetD1_2: D1.2 D3.2 R45.1
NetD2_1: D2.1 L3.2 U9.8
NetL2_1: L2.1 U1.34 | length 2.4
  Top Layer w0.2: U1.34@108.3,86.425 109.125,86.425 109.5,86.05 L2.1@110.575,86.05
NetL6_1: L6.1 U19.29 | length 4.2
  Top Layer w0.2: U19.29@43.075,25.275 43.456,25.275 43.53,25.201 44.076,25.201 45.192,26.317 45.192,27.517 L6.1@45.475,27.8
NetL7_1: L7.1 U19.7 | length 0.7
  Top Layer w0.2: 37.428,24.875 U19.7@38.175,24.875
NetL8_1: L8.1 U22.7 | length 3.6
  Top Layer w0.3: U22.7@16.4,24.05 L8.1@20,24.05
NetL9_1: L9.1 U19.25 | length 1
  Top Layer w0.2: U19.25@43.075,23.675 43.525,23.675 43.549,23.651 44.076,23.651 44.1,23.675
NetL11_1: L11.1 U19.11 | length 1
  Top Layer w0.2: 37.275,22.95 37.6,23.275 U19.11@38.175,23.275
NetL12_2: L12.2 U23.2 U24.2 | length 25
  Top Layer w0.2: L12.2@62.775,19.35 62.85,19.275 v1(63.55,19.275) 63.75,19.275 64.135,19.66 U24.2@65.725,19.66 ; v1(81.854,18.851) 81.854,18.854 82.685,19.685 U23.2@84.725,19.685
  Signal Layer 2 w0.2: v1(63.55,19.275) 63.55,19.325 63.575,19.35 77.295,19.35 77.37,19.425 81.225,19.425 81.799,18.851 v1(81.854,18.851)
NetLD1_1: LD1.1 R152.1 | length 1
  Bottom Layer w0.1: LD1.1@7.95,14.15 R152.1@8.975,14.15
NetLD2_1: LD2.1 R157.1 | length 36.6
  Top Layer w0.1: R157.1@63,7.325 63,7.23 63.205,7.025 63.3,7.025 63.5,6.825 v1(68.725,6.825)
  Bottom Layer w0.1: v1(68.725,6.825) 68.725,9.225 70.25,10.75 72.9,10.75 74.475,12.325 83.275,12.325 84.425,11.175 87.175,11.175 88.65,12.65 LD2.1@88.65,18.3 LD2.1@88.47,18.48
NetLD3_1: LD3.1 R172.1 | length 1.2
  Bottom Layer w0.1: R172.1@3.305,84.388 LD3.1@3.305,85.563
NetLD4_1: LD4.1 R174.1 | length 1.3
  Bottom Layer w0.1: R174.1@3.205,74.888 LD4.1@3.205,76.163
NetLD5_1: LD5.1 R125.1 | length 2.2
  Top Layer w0.1: R125.1@120.525,27.6 v1(121.625,27.6)
  Bottom Layer w0.1: LD5.1@120.525,27.6 v1(121.625,27.6)
NetLD5_2: LD5.2 R117.1 | length 2.1
  Top Layer w0.1: R117.1@120.525,29.1 v1@121.5,29.1
  Bottom Layer w0.1: LD5.2@120.525,29.1 v1(121.625,29.1)
NetLD6_1: LD6.1 R184.2 | length 1.4
  Bottom Layer w0.1: R184.2@44.525,6.275 LD6.1@44.525,7.675
NetLD7_1: LD7.1 R183.2 | length 1.4
  Bottom Layer w0.1: R183.2@52.75,6.275 LD7.1@52.75,7.675
NetR3_1: R3.1 TP19.1 U2.A6 U3.7 | length 14.6
  Top Layer w0.1: U2.A6@33.975,87.75 34.6,87.75 34.625,87.725 37.75,87.725 38.66,86.815 R3.1@39.765,86.815 39.835,86.815 40.04,86.61 U3.7@40.04,85.365 40.04,84.599 43.114,81.525 TP19.1@44.823,81.525
NetR4_1: R4.1 TP10.1 U2.F3 U3.6 | length 29.5
  Top Layer w0.1: v1(41.8,88.475) 41.8,87.075 41.54,86.815 R4.1@40.84,86.815 40.745,86.815 40.54,86.61 U3.6@40.54,85.365 40.54,84.494 41.258,83.775 43.848,83.775 TP10.1@44.823,84.75
  Signal Layer 1 w0.1: v1(27.75,88.525) 29.3,88.525 29.775,89 31.898,89 31.948,88.95 v3(31.975,88.95)
  Signal Layer 2 w0.1: v1(27.75,88.525) 29.25,88.525 29.75,89.025 30.629,89.025 31.879,87.775 41.1,87.775 v1(41.8,88.475)
NetR5_2: R5.2 U2.B4 | length 2.3
  Top Layer w0.1: v3(34.4,88.07) 35.445,88.07 R5.2@35.6,88.225
  Signal Layer 1 w0.1: v3(33.575,88.55) 34.055,88.07 v3(34.4,88.07)
NetR6_1: R6.1 U3.5 | length 1.1
  Top Layer w0.1: U3.5@41.04,85.365 R6.1@42.14,85.365
NetR7_2: R7.2 U5.13 | length 2.5
  Top Layer w0.1: R7.2@66.475,86.35 66.475,85.8 67.325,84.95 U5.13@67.325,84.225
NetR8_2: R8.2 U5.12 | length 2.3
  Top Layer w0.1: R8.2@67.55,86.35 67.55,85.55 67.975,85.125 U5.12@67.975,84.225
NetR9_2: R9.2 U5.11 | length 2.1
  Top Layer w0.1: U5.11@68.625,84.225 R9.2@68.625,86.35
NetR10_2: R10.2 U5.9 | length 2.1
  Top Layer w0.1: U5.9@69.925,84.225 R10.2@69.925,86.35
NetR11_2: R11.2 U5.8 | length 2.3
  Top Layer w0.1: U5.8@70.575,84.225 70.575,85 71,85.425 R11.2@71,86.35
NetR12_2: R12.2 U5.15 | length 2.2
  Top Layer w0.1: R12.2@63.65,83.6 64.675,83.6 64.95,83.325 U5.15@65.775,83.325
NetR19_2: R19.2 U5.16 | length 2.2
  Top Layer w0.1: R19.2@63.65,82.525 64.65,82.525 64.8,82.675 U5.16@65.775,82.675
NetR22_1: R22.1 U4.1 U4.24 | length 14
  Top Layer w0.1: R22.1@16.775,75.65 U4.24@19.65,75.65 v1(19.65,75.175) ; U4.1@19.65,84.85 v1(19.65,85.35)
  Bottom Layer w0.1: v1(19.65,75.175) v1(19.65,85.35)
NetR23_1: R23.1 U4.25 U4.48 | length 14
  Top Layer w0.1: v1(25.25,85.35) 25.25,84.9 U4.48@25.3,84.85 ; v1(25.3,75.175) U4.25@25.3,75.65 R23.1@28.1,75.65
  Bottom Layer w0.1: v1(25.25,85.35) 25.3,85.3 v1(25.3,75.175)
NetR28_2: R28.2 U7.15 | length 1.9
  Top Layer w0.1: R28.2@46.275,65.1 46.275,64.525 46.575,64.225 U7.15@46.575,63.35
NetR29_1: R29.1 R30.2 U7.14 | length 2.9
  Top Layer w0.1: U7.14@47.075,63.35 47.075,64.25 47.35,64.525 R29.1@47.35,65.1 R30.2@48.425,65.1
NetR32_1: R32.1 R36.2 U7.11 | length 4.9
  Top Layer w0.1: U7.11@48.275,62.15 48.975,62.15 50.475,63.65 R36.2@51.525,63.65 R32.1@51.525,64.725
NetR38_1: R38.1 U7.10 | length 3.6
  Top Layer w0.1: U7.10@48.275,61.65 49.175,61.65 50.1,62.575 R38.1@51.525,62.575
NetR41_2: R41.2 R43.1 U7.8 | length 6.5
  Top Layer w0.1: U7.8@48.275,60.65 49.838,60.65 49.889,60.65 49.989,60.75 49.989,60.9 50.089,61 50.289,61 50.389,60.9 50.389,59.831 50.489,59.731 50.689,59.731 50.789,59.831 50.789,60.55 50.889,60.65 51.09,60.65 51.45,60.65 R41.2@51.525,60.575 R43.1@51.525,59.5
NetR44_2: R44.2 U9.2 | length 2.1
  Top Layer w0.1: R44.2@83.025,59.425 83.175,59.575 U9.2@85.075,59.575
NetR47_1: R47.1 U7.24 | length 2.9
  Top Layer w0.1: R47.1@42.525,58.7 43.375,58.7 43.65,58.975 43.65,59.675 44.125,60.15 U7.24@44.375,60.15
NetR48_1: R48.1 R51.2 U7.7 | length 5
  Top Layer w0.1: U7.7@48.275,60.15 49.1,60.15 50.825,58.425 R48.1@51.525,58.425 R51.2@51.525,57.35
NetR50_2: R50.2 U7.5 | length 2
  Top Layer w0.1: R50.2@46.375,57.75 46.375,58.125 47.075,58.825 U7.5@47.075,59.45
NetR53_2: R53.2 R57.2 U9.7 | length 7.2
  Top Layer w0.1: R57.2@86.675,55.45 R53.2@86.675,56.525 v1(88.275,56.525) ; U9.7@87.875,59.575 88.45,59.575 v1(88.75,59.875)
  Bottom Layer w0.1: v1(88.275,56.525) 88.275,59.4 v1(88.75,59.875)
NetR54_1: R54.1 U12.A7 | length 2.6
  Top Layer w0.1: R54.1@108.425,54.85 108.425,54.05 108.825,53.65 108.825,52.584 108.804,52.562 108.804,52.479 U12.A7@108.775,52.45
NetR55_1: R55.1 U12.C10 | length 4.6
  Top Layer w0.1: U12.C10@110.725,51.15 111.05,51.475 111.439,51.475 111.7,51.736 111.7,53.4 112.275,53.975 R55.1@112.275,54.85
NetR56_2: R56.2 TP38.1 U12.B14 | length 7.7
  Top Layer w0.1: U12.B14@113.325,51.8 113,52.125 113,52.85 113.775,53.625 R56.2@113.775,54.85 116.775,54.85 TP38.1@117.6,55.675
NetR64_2: R64.2 U14.C10 | length 16.9
  Top Layer w0.09: U14.C10@72.475,39.65 72.488,39.638 72.488,39.163 v2@72.5,39.15
  Top Layer w0.1: v1(80.304,48.852) 81.123,48.852 R64.2@81.25,48.725
  Bottom Layer w0.09: 72.425,43.125 72.425,39.444 72.443,39.426 72.443,39.282 v2(72.5,39.225)
  Bottom Layer w0.1: 72.425,43.125 72.425,45.233 74.267,47.075 78.527,47.075 80.177,48.725 v1@80.3,48.725
NetR65_2: R65.2 X1.1 | length 1.3
  Top Layer w0.1: R65.2@98.525,47.475 99.625,47.475 X1.1@99.8,47.3
NetR66_2: R66.2 U12.J15 | length 3.2
  Top Layer w0.1: U12.J15@113.975,47.25 115,47.25 115.875,46.375 R66.2@116.85,46.375
NetR77_2: R77.2 U13.15 | length 2.1
  Top Layer w0.1: R77.2@46.275,42.725 46.575,42.725 U13.15@46.575,40.975
NetR78_1: R78.1 R79.2 U13.14 | length 3.1
  Top Layer w0.1: U13.14@47.075,40.975 47.075,42.725 R78.1@47.35,42.725 R79.2@48.425,42.725
NetR83_1: R83.1 R86.2 U13.11 | length 4.9
  Top Layer w0.1: U13.11@48.275,39.775 48.9,39.775 50.4,41.275 R86.2@51.525,41.275 R83.1@51.525,42.35
NetR84_2: R84.2 U12.L4 | length 8
  Top Layer w0.1: R84.2@101.775,42.325 102.3,42.325 102.55,42.575 102.55,43.6 103.8,44.85 104.45,44.85 104.575,44.975 106.889,44.975 107.15,45.236 107.15,45.625 U12.L4@106.825,45.95
NetR85_2: R85.2 U14.J5 | length 11.8
  Top Layer w0.09: R85.2@61.875,41.375 v2(62.425,41.375) ; U14.J5@69.975,36.65 70.167,36.65 70.292,36.775 v2(70.35,36.775) v2@70.392,36.775
  Bottom Layer w0.09: v2(62.425,41.375) 63.025,40.775 64.5,40.775 64.65,40.925 66.575,40.925 68.075,39.425 68.075,38 69.025,37.05 70.075,37.05 v2(70.35,36.775)
NetR87_2: R87.2 R94.1 U12.N3 | length 7.9
  Top Layer w0.1: R94.1@100.875,40.175 100.875,40.3 101.775,41.2 R87.2@101.775,41.25 102.725,41.25 103.25,41.775 103.25,42.925 104.65,44.325 105.85,44.325 U12.N3@106.175,44.65
NetR91_2: R91.2 TP48.1 U12.R13 | length 6.3
  Top Layer w0.1: U12.R13@112.675,43.35 112.675,42.725 113.35,42.05 R91.2@113.35,41.15 114.3,41.15 114.775,40.675 ; 114.776,40.675 115.025,40.426 115.45,40 TP48.1@115.45,38.75
NetR93_1: R93.1 U13.10 | length 3.6
  Top Layer w0.1: U13.10@48.275,39.275 49.225,39.275 50.15,40.2 R93.1@51.525,40.2
NetR96_1: R96.1 U14.J2 | length 10.4
  Top Layer w0.075: 65.175,37.375 65.95,36.6 67.419,36.6 67.619,36.4 68.225,36.4 U14.J2@68.475,36.65
  Top Layer w0.1: R96.1@59.275,38.95 59.925,38.95 60.325,38.55 64,38.55 65.175,37.375
NetR98_2: R98.2 R100.1 U13.8 | length 4.4
  Top Layer w0.1: U13.8@48.275,38.275 51.45,38.275 R98.2@51.525,38.2 R100.1@51.525,37.125
NetR101_1: R101.1 U13.24 | length 2.5
  Top Layer w0.1: R101.1@42.525,36.325 42.525,36.42 43.517,37.413 43.589,37.413 43.891,37.715 44.315,37.715 U13.24@44.375,37.775
NetR102_1: R102.1 R109.2 U13.7 | length 5
  Top Layer w0.1: U13.7@48.275,37.775 49.2,37.775 50.925,36.05 R102.1@51.525,36.05 R109.2@51.525,34.975
NetR103_1: R103.1 U14.L3 | length 6.1
  Top Layer w0.075: 65.175,35.397 68.722,35.397 U14.L3@68.975,35.65
  Top Layer w0.09: 64.5,35.95 65.053,35.397 65.175,35.397
  Top Layer w0.1: R103.1@63.175,35.95 64.5,35.95
NetR105_2: R105.2 U13.4 | length 1.7
  Top Layer w0.1: R105.2@46.575,35.4 U13.4@46.575,37.075
NetR106_2: R106.2 R107.2 U13.5 | length 3
  Top Layer w0.1: U13.5@47.075,37.075 47.075,36.425 47.65,35.85 R106.2@47.65,35.4 R107.2@48.725,35.4
NetR112_2: R112.2 U14.R20 | length 4.4
  Top Layer w0.075: U14.R20@77.474,33.65 77.675,33.85 77.825,33.85 77.862,33.887 ; 77.863,33.887 77.872,33.896 78.271,33.896 78.287,33.896 78.36,33.97 78.668,33.97 78.845,33.793 78.845,33.58 78.96,33.465 79.038,33.465 79.325,33.178 79.325,33.177 79.341,33.161 79.341,32.957 79.557,32.741 79.557,32.419 80.075,31.9 R112.2@80.5,31.9
NetR114_2: R114.2 U19.1 | length 3.6
  Top Layer w0.1: R114.2@36.4,30.1 36.4,29.528 37.375,28.553 37.375,28.549 37.724,28.2 37.776,28.2 38.134,27.842 38.134,27.316 U19.1@38.175,27.275
NetR115_2: R115.2 U19.37 | length 2.2
  Top Layer w0.2: U19.37@41.625,28.025 41.625,28.528 41.752,28.655 41.752,29.973 R115.2@41.625,30.1
NetR128_1: R128.1 U14.W12 | length 5.3
  Top Layer w0.075: 73.263,27.725 73.151,27.836 73.151,30.081 73.228,30.159 73.228,31.403 U14.W12@73.475,31.65
  Top Layer w0.1: 73.263,27.725 73.263,26.83 73.468,26.625 R128.1@73.475,26.625
NetR135_1: R135.1 R136.2 U22.3 | length 2.1
  Top Layer w0.1: R135.1@11.475,23.325 11.55,23.4 12.45,23.4 R136.2@12.525,23.325 12.6,23.4 U22.3@13.45,23.4
NetR140_2: R140.2 U19.13
NetR142_1: R142.1 R143.2 U20.11 | length 6.3
  Top Layer w0.1: R142.1@108.025,19.575 R143.2@109.475,19.575 109.475,20.525 109.85,20.9 112.525,20.9 112.9,21.275 U20.11@112.9,21.475
NetR146_2: R146.2 U33.35 | length 3.8
  Top Layer w0.1: U33.35@59.15,14.25 59.775,14.25 61.625,16.1 61.925,16.1 R146.2@62.1,16.275
NetR148_2: R148.2 R150.1 U25.6 | length 3.3
  Top Layer w0.1: U25.6@22.345,17.36 23.32,17.36 23.52,17.16 24.495,17.16 R150.1@24.495,16.085
NetR153_1: R153.1 SW1.6 | length 13.1
  Top Layer w0.1: SW1.6@35.3,12.485 35.275,12.46 35.275,10.15 37.4,8.025 R153.1@45.1,8.025
NetR154_1: R154.1 SW1.7 | length 9.2
  Top Layer w0.1: SW1.7@37.8,12.485 37.8,11.225 39.45,9.575 R154.1@45.1,9.575
NetR155_1: R155.1 SW1.8 | length 6.2
  Top Layer w0.1: SW1.8@40.3,12.485 40.3,11.225 40.6,10.925 R155.1@45.1,10.925
NetR156_2: R156.2 R157.2 U33.28 | length 5
  Top Layer w0.1: U33.28@59.15,10.75 59.475,10.75 61.65,8.575 61.925,8.575 R156.2@62.1,8.4 R157.2@62.1,7.325
NetR158_2: R158.2 R164.1 R166.2 U33.22 | length 6.1
  Top Layer w0.1: R166.2@53.875,5.125 R164.1@53.875,6.2 R158.2@53.875,7.275 53.875,7.825 54.125,8.075 54.7,8.075 55.9,9.275 U33.22@55.9,10
NetR159_2: R159.2 R165.1 R167.2 U33.24 | length 5.4
  Top Layer w0.1: R167.2@55.625,5.125 R165.1@55.625,6.2 R159.2@55.625,7.275 55.725,7.375 55.725,7.925 56.9,9.1 U33.24@56.9,10
NetR160_2: R160.2 R161.1 U33.25 | length 3.7
  Top Layer w0.1: U33.25@57.4,10 57.4,7.475 R160.2@57.475,7.4 R161.1@58.55,7.4
NetR162_2: R162.2 U33.26 | length 3.7
  Top Layer w0.1: U33.26@57.9,10 57.9,9.125 58.625,8.4 59.275,8.4 59.625,8.05 R162.2@59.625,7.4
NetR163_1: R163.1 U33.27 | length 4
  Top Layer w0.1: U33.27@58.4,10 58.4,9.725 59.25,8.875 59.975,8.875 60.7,8.15 R163.1@60.7,7.4
NetR179_2: R179.2 U17.L8 | length 2.1
  Top Layer w0.2: U17.L8@89.55,31.7 v2(89.95,31.3)
  Bottom Layer w0.2: v2(89.95,31.3) 90.35,30.9 90.35,30.025 R179.2@90.45,29.925
NetR186_1: R186.1 U22.5 | length 2.2
  Top Layer w0.1: U22.5@16.4,22.75 16.5,22.75 16.625,22.625 16.625,22.525 17.15,22 R186.1@18.275,22
NetR190_2: R190.2 U1.37 | length 5.2
  Top Layer w0.1: U1.37@108.3,87.775 112.6,87.775 112.97,87.405 113.07,87.405 R190.2@113.275,87.2
NetR191_1: R191.1 R192.1 U14.L2 | length 76.8
  Top Layer w0.075: 65.175,36.675 66.284,35.566 68.266,35.566 68.327,35.627 68.452,35.627 U14.L2@68.475,35.65
  Top Layer w0.2: R192.1@62.9,37.725 v1(63.65,37.725) 64.125,37.725 65.175,36.675
  Top Layer w0.5: v1(9.15,26.825) 9.15,26.811 9.45,26.511 R191.1@9.45,25.825
  Signal Layer 2 w0.5: v1(9.15,26.825) 9.15,28.575 10.2,29.625 10.2,36.325 13.275,39.4 31.125,39.4 32.325,38.2 35.475,38.2 37.2,39.925 37.825,39.925 40.05,42.15 43.988,42.15 45.188,40.95 49.175,40.95 50.575,39.55 53.216,39.55 53.866,40.2 61.175,40.2 v1(63.65,37.725)
NetTP2_1: TP2.1 U1.6 | length 8.1
  Top Layer w0.1: TP2.1@101.375,95.1 101.375,92.25 101.525,92.1 103.9,92.1 105.375,90.625 U1.6@105.375,90.025
NetTP5_1: TP5.1 U1.7 | length 6.9
  Top Layer w0.1: TP5.1@99.5,92.75 100.35,91.9 103.675,91.9 104.925,90.65 U1.7@104.925,90.025
NetTP12_1: TP12.1 U2.G5 U4.47 | length 10.7
  Top Layer w0.1: U4.47@25.3,84.45 26.3,84.45 26.525,84.675 26.525,87.445 ; TP12.1@25.3,87.55 25.405,87.445 26.525,87.445 ; U2.G5@31.575,88.15 31.548,88.15 31.498,88.2 30.905,88.2 30.15,87.445 26.525,87.445
NetTP16_1: TP16.1 U2.E5 U4.46 | length 13.8
  Top Layer w0.1: U4.46@25.3,84.05 27.125,84.05 27.425,84.35 31,84.35 ; TP16.1@31,85.5 31,84.35 ; v3(33.725,86.325) 31.75,84.35 31,84.35
  Signal Layer 1 w0.1: v3(32.375,88.15) 32.779,88.15 33.059,88.43 33.291,88.43 33.675,88.046 33.675,86.464 33.694,86.444 33.694,86.356 v3(33.725,86.325)
NetTP18_1: TP18.1 U1.17 | length 7
  Top Layer w0.1: TP18.1@96.5,85.25 99.2,85.25 101.725,87.775 U1.17@102.45,87.775
NetTP20_1: TP20.1 U2.G4 U4.44 | length 23.3
  Top Layer w0.1: U2.G4@31.575,88.55 30.972,88.55 30.772,88.35 30.067,87.645 26.13,87.645 25.65,88.125 24.55,88.125 23.65,87.225 23.65,83.525 23.925,83.25 U4.44@25.3,83.25 26.775,83.25 27.525,84 TP20.1@34,84
NetTP22_1: TP22.1 U1.18 | length 5.2
  Top Layer w0.1: TP22.1@99.5,83.75 99.5,85.1 101.725,87.325 U1.18@102.45,87.325
NetTP24_1: TP24.1 U2.E4 U4.43 | length 20.9
  Top Layer w0.1: U4.43@25.3,82.85 29.625,82.85 30.05,83.275 31,83.275 ; TP24.1@31,82.5 31,83.275 ; v1(35.475,86.55) 35.475,84.175 34.575,83.275 31,83.275
  Signal Layer 1 w0.1: v3(32.375,88.55) 32.695,88.87 33.207,88.87 33.367,89.03 34.04,89.03 34.17,89.16 34.17,89.68 34.44,89.95 34.85,89.95 35.475,89.325 v1(35.475,86.55)
NetTP26_1: TP26.1 U2.F4 U4.41 | length 21.5
  Top Layer w0.1: U4.41@25.3,82.05 v1(26.725,82.05) 27.725,82.05 28.325,81.45 30.65,81.45 31.1,81 TP26.1@34,81
  Signal Layer 1 w0.1: v1(26.725,88.475) 27.55,87.65 30.05,87.65 30.95,88.55 v3(31.975,88.55)
  Bottom Layer w0.1: v1(26.725,82.05) v1(26.725,88.475)
NetTP31_1: TP31.1 U2.G7 U4.36 | length 14.1
  Top Layer w0.1: U4.36@25.3,80.05 27.425,80.05 27.654,80.279 v1(30.376,80.279) 30.376,80.199 31,79.575 TP31.1@31,79.5 ; v1(30.45,86.8) 31.025,86.8 U2.G7@31.575,87.35
  Bottom Layer w0.1: v1(30.376,80.279) 30.376,86.726 v1(30.45,86.8)
NetTP33_1: TP33.1 U5.25 | length 9
  Top Layer w0.1: U5.25@68.625,78.525 68.625,76.925 68.225,76.525 68.225,74.303 69.078,73.45 TP33.1@72.525,73.45
NetTP34_1: TP34.1 U5.22 | length 5.2
  Top Layer w0.1: TP34.1@65.95,73.675 65.95,76.375 66.675,77.1 U5.22@66.675,78.525
NetTP35_1: TP35.1 U5.24 | length 9
  Top Layer w0.1: U5.24@67.975,78.525 67.975,73.8 TP35.1@70.975,70.8
NetTP36_1: TP36.1 U5.23 | length 7.3
  Top Layer w0.1: U5.23@67.325,78.525 67.325,77.1 67.5,76.925 67.5,73.725 67.925,73.3 TP36.1@67.925,71.45
NetTP45_1: TP45.1 U14.P18 | length 22.9
  Top Layer w0.1: v2@76.47,34.691 76.493,34.669 76.493,34.561 76.47,34.539 76.47,34.155 U14.P18@76.475,34.15 ; v1(92.75,42.4) TP45.1@92.75,43.25
  Signal Layer 2 w0.1: v2(76.55,34.7) 77.55,34.7 77.925,35.075 77.925,38.575 80.075,40.725 81.275,40.725 91.025,40.725 92.7,42.4 v1(92.75,42.4)
NetTP46_1: TP46.1 U14.P17 | length 27.1
  Top Layer w0.09: v2(75.5,34.125) 75.95,34.125 U14.P17@75.975,34.15
  Top Layer w0.1: v1(95.4,42.4) TP46.1@95.4,43.25
  Signal Layer 2 w0.1: v2(75.5,34.125) 77.85,34.125 78.125,34.4 78.125,38.475 80.175,40.525 81.275,40.525 93.475,40.525 95.35,42.4 v1(95.4,42.4)
NetTP52_1: TP52.1 U20.1 U21.16 | length 25.2
  Top Layer w0.1: U21.16@102.075,25.325 102.075,28.4 v1(102.95,29.275) 104.825,29.275 TP52.1@104.9,29.35 ; U20.1@114.9,25.325 114.9,25.575 117.05,27.725 v1(117.05,29.275)
  Signal Layer 2 w0.1: v1(102.95,29.275) v1(117.05,29.275)
NetTP55_1: TP55.1 U20.3 U21.15 | length 16.4
  Top Layer w0.1: U21.15@102.575,25.45 102.575,26.7 103.6,27.725 v1(107.225,27.725) 107.6,27.35 TP55.1@107.6,26.55 ; v1(113.4,27.725) 113.4,27.075 113.9,26.575 U20.3@113.9,25.325
  Signal Layer 2 w0.1: v1(107.225,27.725) v1(113.4,27.725)
NetTP57_1: TP57.1 U14.W3 | length 6.8
  Top Layer w0.075: 67.05,27.725 67.05,28.35 68.725,30.025 68.725,31.275 68.952,31.502 68.952,31.627 U14.W3@68.975,31.65
  Top Layer w0.1: TP57.1@66.775,25.8 66.775,26.4 67.05,26.675 67.05,27.725
NetU2_C6: U2.C6 U4.27 | length 28
  Top Layer w0.1: v1(21.425,76.9) 22.25,76.9 22.7,76.45 U4.27@25.3,76.45
  Signal Layer 1 w0.1: v3(33.175,87.75) 33.175,85.95 33.525,85.6 v1(33.975,85.6)
  Signal Layer 2 w0.1: v1(21.425,84.925) 22.552,84.925 22.752,85.125 23.479,85.125 23.829,84.775 25.376,84.775 25.526,84.925 32.025,84.925 32.225,85.125 ; 32.226,85.125 32.475,85.374 ; 32.475,85.375 32.7,85.6 v1(33.975,85.6)
  Bottom Layer w0.1: v1(21.425,76.9) v1(21.425,84.925)
NetU2_C7: U2.C7 U4.26 | length 25.8
  Top Layer w0.1: v1(22.375,75.8) 22.625,76.05 U4.26@25.3,76.05 ; v1(32.05,85.55) 32.35,85.55 33.175,86.375 U2.C7@33.175,87.35
  Signal Layer 2 w0.1: v1(22.2,85.35) 24.625,85.35 25.05,85.775 25.426,85.775 26.076,85.125 31.625,85.125 v1(32.05,85.55)
  Bottom Layer w0.1: v1(22.2,85.35) 22.164,85.314 22.164,83.021 22,82.857 22,80.9 22.375,80.525 22.375,77.851 22.4,77.826 22.4,77.474 22.4,75.825 v1(22.375,75.8)
NetU2_D6: U2.D6 U4.30 | length 22.9
  Top Layer w0.1: v1(23.15,77.65) 23.2,77.7 25.25,77.7 U4.30@25.3,77.65
  Signal Layer 1 w0.1: v3(32.775,87.75) 32.775,85.625 v1(33.3,85.1)
  Signal Layer 2 w0.1: v1(22.925,84.575) 25.6,84.575 25.7,84.675 32.875,84.675 v1(33.3,85.1)
  Bottom Layer w0.1: v1(22.925,84.575) 22.925,82.655 22.975,82.605 22.975,82.199 ; 22.976,82.198 22.976,81.372 23.425,80.922 23.425,77.925 v1(23.15,77.65)
NetU2_D7: U2.D7 U4.29 | length 20.3
  Top Layer w0.1: v1(24.125,77.25) U4.29@25.3,77.25 ; v1(32.35,86.3) 32.775,86.725 U2.D7@32.775,87.35
  Signal Layer 2 w0.1: v1(24.1,85.775) 24.4,86.075 25.45,86.075 25.8,85.725 28.813,85.725 29.263,86.175 30.86,86.175 30.985,86.3 v1(32.35,86.3)
  Bottom Layer w0.1: v1(24.1,85.775) 24.9,84.975 24.9,78.025 v1(24.125,77.25)
NetU2_E6: U2.E6 U4.32 | length 14.9
  Top Layer w0.1: U4.32@25.3,78.45 25.325,78.425 26.975,78.425 27.55,79 v1(28.7,79)
  Signal Layer 1 w0.1: v1(29.525,85.6) 30.95,85.6 32.375,87.025 v3(32.375,87.75)
  Bottom Layer w0.1: v1(28.7,79) 28.926,79.226 28.926,80.199 28.701,80.424 28.701,84.776 v1(29.525,85.6)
